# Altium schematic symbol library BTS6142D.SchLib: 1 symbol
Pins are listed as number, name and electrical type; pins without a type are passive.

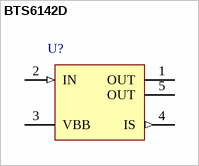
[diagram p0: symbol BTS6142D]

## BTS6142D
designator U?
Smart High-Side Power Switch PROFET, 12 mOhm, 1 Channel, 8.5 A Load Current, -40 to 150 degC, PG-TO252-5-11, Reel, Green; Manufacturer: Infineon; PartNumber: BTS6142D; Channels: 1; Green: TRUE; Group: Automotive Qualified; Load Current (typ): 8.5 A; Ptot (max): 50 W; Recommended Operating Voltage Max.: 24 V; Recommended Operating Voltage Min.: 5.5 V; RON @ 25degreesC: 12 mOhm; RON(max) @ 150degreesC: 22 mOhm; toff (max): 600 us
footprint INF-PG-TO252-5-11_N (DPAK, 5-Leads, Body 6.5x6.12mm, Pitch 1.14mm, IPC Medium Density)
footprint INF-PG-TO252-5-11_L (DPAK, 5-Leads, Body 6.5x6.12mm, Pitch 1.14mm, IPC High Density)
footprint INF-PG-TO252-5-11_M (DPAK, 5-Leads, Body 6.5x6.12mm, Pitch 1.14mm, IPC Low Density)
pins: 1 OUT (hiz) "Output; output to the load; pin 1 and 5 must be externally shorted.", 2 IN (in) "Input; activates the power switch if shorted to ground.", 3 VBB (power) "Supply Voltage; positive power supply voltage; tab and pin 3 are internally shorted.", 4 IS (out) "Sense Output; Diagnostic feedback; provides at normal operation a sense current proportional to the load current; in case of overload, overtemperature and/or short circuit a defined current is provided.", 5 OUT (hiz) "Output; output to the load; pin 1 and 5 must be externally shorted."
